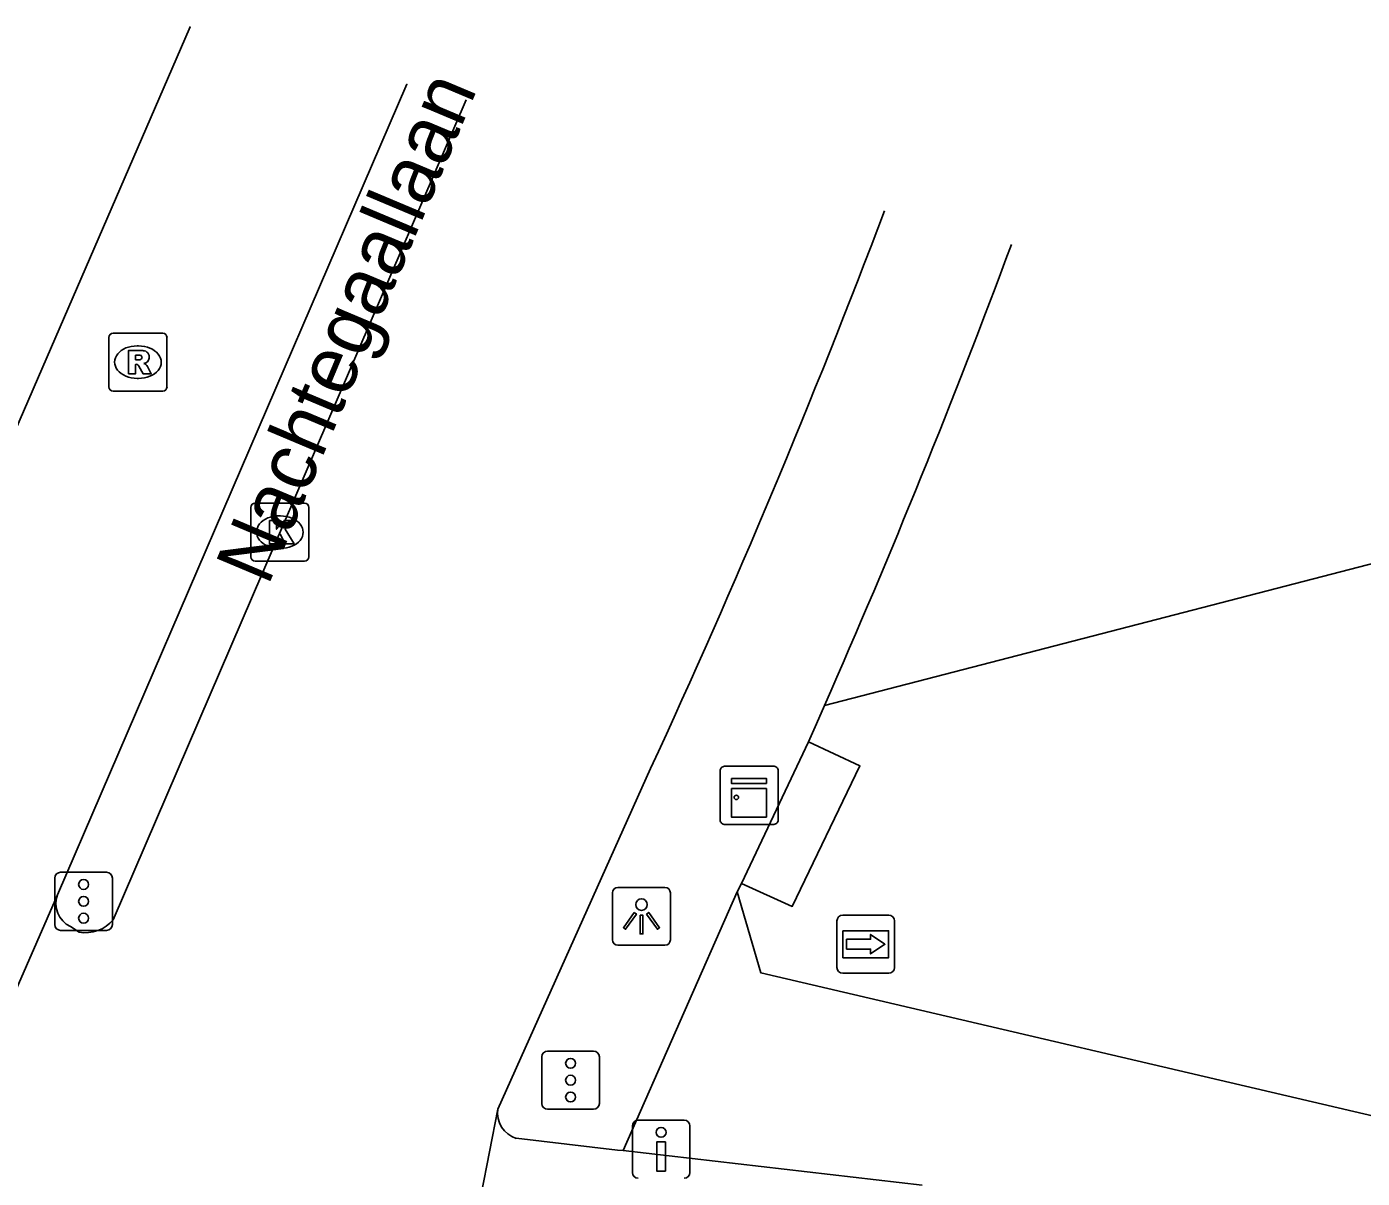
# Model space of a CAD drawing. Extents: x 161771 to 163125, y 382479 to 383177.
# Drawn here: x 161849.91 to 161872.88, y 383156.4 to 383176.21 of the extents above; entities that cross this region are included whole.
import ezdxf

# ---------------------------------------------------------------- set-up
doc = ezdxf.new("R2010")
doc.units = 0
for name, color, linetype in [('IMGEO_Drukknoppaal', 7, 'Continuous'), ('IMGEO_Fietspad_gesloten', 7, 'Continuous'), ('IMGEO_Groenvoorziening', 7, 'Continuous'), ('IMGEO_Kast', 7, 'Continuous'), ('IMGEO_Kolk', 7, 'Continuous'), ('IMGEO_Lichtpunt', 7, 'Continuous'), ('IMGEO_Openbare_ruimte_label', 7, 'Continuous'), ('IMGEO_Rijbaan_lokaal_gesloten', 7, 'Continuous'), ('IMGEO_Rioolput', 7, 'Continuous'), ('IMGEO_Verkeersregelinstallatiepaal', 7, 'Continuous'), ('IMGEO_Voetpad_open', 7, 'Continuous'), ('IMGEO_Wegwijzer', 7, 'Continuous')]:
    doc.layers.add(name, color=color, linetype=linetype)

msp = doc.modelspace()

# ---------------------------------------------------------------- linework, layer by layer
at = {"layer": 'IMGEO_Drukknoppaal'}
for p, q in [((161860.325, 383156.5), (161860.325, 383157.3)), ((161860.325, 383157.3), (161860.325, 383156.5)), ((161860.425, 383157.4), (161861.215, 383157.4)), ((161861.215, 383157.4), (161860.425, 383157.4)), ((161861.315, 383157.3), (161861.315, 383156.5)), ((161861.315, 383156.5), (161861.315, 383157.3))]:
    msp.add_line(p, q, dxfattribs=at)
msp.add_lwpolyline([(161860.895, 383157.025), (161860.895, 383156.525), (161860.745, 383156.525), (161860.745, 383157.025), (161860.895, 383157.025)], dxfattribs=at)
msp.add_circle((161860.82, 383157.19), 0.085, dxfattribs=at)
for centre, start, end in [((161860.425, 383157.3), 90, 180), ((161860.425, 383157.3), 90, 180), ((161861.215, 383157.3), 0, 90), ((161861.215, 383157.3), 360, 90), ((161860.425, 383156.5), 180, 270), ((161860.425, 383156.5), 180, 270), ((161861.215, 383156.5), 270, 0), ((161861.215, 383156.5), 270, 0)]:
    msp.add_arc(centre, 0.1, start, end, dxfattribs=at)
at = {"layer": 'IMGEO_Fietspad_gesloten'}
for points in [[(161852.715, 383176.208), (161852.715, 383176.208), (161847.31, 383163.743), (161846.264, 383161.291), (161846.152, 383161.028)], [(161856.447, 383175.219), (161856.447, 383175.219), (161850.438, 383161.277)], [(161858.326, 383157.088), (161860.068, 383156.887), (161860.165, 383156.876)], [(161865.311, 383156.282), (161860.165, 383156.876)]]:
    msp.add_lwpolyline(points, dxfattribs=at)
msp.add_arc((161858.469, 383157.53), 0.465, 172.5238, 252.0789, dxfattribs=at)
at = {"layer": 'IMGEO_Groenvoorziening'}
for points in [[(161863.63, 383164.532), (161876.472, 383167.861), (161877.756, 383169.569), (161877.756, 383169.569)], [(161863.354, 383163.909), (161864.239, 383163.493), (161863.075, 383161.077), (161862.205, 383161.47)]]:
    msp.add_lwpolyline(points, dxfattribs=at)
at = {"layer": 'IMGEO_Kast'}
for p, q in [((161861.91, 383163.488), (161862.751, 383163.488)), ((161862.751, 383163.488), (161861.91, 383163.488)), ((161861.835, 383162.563), (161861.835, 383163.404)), ((161861.835, 383163.404), (161861.835, 383162.563)), ((161862.835, 383163.413), (161862.835, 383162.572)), ((161862.835, 383162.572), (161862.835, 383163.413)), ((161862.76, 383162.488), (161861.919, 383162.488)), ((161861.919, 383162.488), (161862.76, 383162.488))]:
    msp.add_line(p, q, dxfattribs=at)
for points in [[(161862.03, 383163.278), (161862.63, 383163.278), (161862.63, 383163.193), (161862.03, 383163.193), (161862.03, 383163.278)], [(161862.03, 383163.103), (161862.63, 383163.103), (161862.63, 383162.614), (161862.03, 383162.614), (161862.03, 383163.103)]]:
    msp.add_lwpolyline(points, dxfattribs=at)
msp.add_circle((161862.114, 383162.952), 0.0377, dxfattribs=at)
for centre, start, end in [((161861.913, 383163.41), 92.4484, 184.2845), ((161861.913, 383163.41), 92.4484, 184.2845), ((161862.757, 383163.41), 2.4484, 94.2845), ((161862.757, 383163.41), 2.4484, 94.2845), ((161861.913, 383162.566), 182.4484, 274.2845), ((161861.913, 383162.566), 182.4484, 274.2845), ((161862.757, 383162.566), 272.4484, 4.2845), ((161862.757, 383162.566), 272.4484, 4.2845)]:
    msp.add_arc(centre, 0.0779, start, end, dxfattribs=at)
at = {"layer": 'IMGEO_Kolk'}
for p, q in [((161853.835, 383168.015), (161854.687, 383168.015)), ((161853.76, 383167.089), (161853.76, 383167.941)), ((161854.248, 383167.795), (161854.273, 383167.795)), ((161854.761, 383167.941), (161854.761, 383167.089)), ((161854.271, 383167.235), (161854.246, 383167.235)), ((161854.687, 383167.015), (161853.835, 383167.015))]:
    msp.add_line(p, q, dxfattribs=at)
for points in [[(161853.835, 383168.015), (161854.687, 383168.015)], [(161853.76, 383167.089), (161853.76, 383167.941)], [(161854.761, 383167.941), (161854.761, 383167.089)], [(161854.081, 383167.715), (161854.204, 383167.715), (161854.204, 383167.564), (161854.334, 383167.715), (161854.498, 383167.715), (161854.352, 383167.564), (161854.505, 383167.315), (161854.353, 383167.315), (161854.268, 383167.479), (161854.204, 383167.412), (161854.204, 383167.315), (161854.081, 383167.315), (161854.081, 383167.715)], [(161854.687, 383167.015), (161853.835, 383167.015)]]:
    msp.add_lwpolyline(points, dxfattribs=at)
for centre, start, end in [((161853.837, 383167.939), 91.552, 178.448), ((161853.837, 383167.939), 91.552, 178.448), ((161854.685, 383167.939), 1.552, 88.448), ((161854.685, 383167.939), 1.552, 88.448), ((161853.837, 383167.091), 181.552, 268.448), ((161853.837, 383167.091), 181.552, 268.448), ((161854.685, 383167.091), 271.552, 358.448), ((161854.685, 383167.091), 271.552, 358.448)]:
    msp.add_arc(centre, 0.0765, start, end, dxfattribs=at)
for centre, major_axis, ratio, start_param, end_param in [((161854.247, 383167.515), (-0.387, 0.002), 0.722429, 4.712389, 7.853982), ((161854.272, 383167.515), (-0.39, 0.002), 0.717154, 1.570796, 4.712389)]:
    msp.add_ellipse(centre, major_axis=major_axis, ratio=ratio, start_param=start_param, end_param=end_param, dxfattribs=at)
at = {"layer": 'IMGEO_Lichtpunt'}
for p, q in [((161860.885, 383161.405), (161860.077, 383161.405)), ((161860.885, 383161.405), (161860.077, 383161.405)), ((161859.983, 383161.31), (161859.983, 383160.503)), ((161859.983, 383161.31), (161859.983, 383160.503)), ((161860.979, 383160.503), (161860.979, 383161.31)), ((161860.979, 383160.503), (161860.979, 383161.31)), ((161860.077, 383160.409), (161860.885, 383160.409)), ((161860.077, 383160.409), (161860.885, 383160.409))]:
    msp.add_line(p, q, dxfattribs=at)
for points in [[(161860.357, 383160.974), (161860.396, 383160.946), (161860.208, 383160.684), (161860.17, 383160.711), (161860.357, 383160.974)], [(161860.459, 383160.926), (161860.506, 383160.926), (161860.506, 383160.604), (161860.459, 383160.604), (161860.459, 383160.926)], [(161860.569, 383160.946), (161860.607, 383160.973), (161860.794, 383160.711), (161860.755, 383160.683), (161860.569, 383160.946)]]:
    msp.add_lwpolyline(points, dxfattribs=at)
msp.add_circle((161860.482, 383161.108), 0.0994, dxfattribs=at)
for centre, start, end in [((161860.077, 383161.31), 90, 180), ((161860.077, 383161.31), 90, 180), ((161860.885, 383161.31), 0, 90), ((161860.885, 383161.31), 0, 90), ((161860.077, 383160.503), 180, 270), ((161860.077, 383160.503), 180, 270), ((161860.885, 383160.503), 270, 0), ((161860.885, 383160.503), 270, 360)]:
    msp.add_arc(centre, 0.0946, start, end, dxfattribs=at)
at = {"layer": 'IMGEO_Rijbaan_lokaal_gesloten'}
for points in [[(161851.391, 383160.847), (161857.465, 383174.949), (161857.465, 383174.949)], [(161858.008, 383157.591), (161860.639, 383163.447)], [(161850.438, 383161.277), (161841.823, 383141.564), (161840.322, 383138.503), (161840.254, 383138.363)], [(161850.66, 383160.732), (161850.806, 383160.634)], [(161857.437, 383154.654), (161858.008, 383157.591)]]:
    msp.add_lwpolyline(points, dxfattribs=at)
for centre, radius, start, end in [((161725.904, 383225.605), 148.382, 335.23443, 339.25215), ((161728.746, 383224.589), 145.364, 339.23, 339.23027), ((161850.835, 383161.121), 0.427, 158.5475, 245.7785), ((161850.919, 383161.234), 0.61, 259.3262, 320.6872)]:
    msp.add_arc(centre, radius, start, end, dxfattribs=at)
at = {"layer": 'IMGEO_Rioolput'}
for p, q in [((161851.318, 383170.013), (161851.318, 383170.865)), ((161851.393, 383170.939), (161852.245, 383170.939)), ((161852.319, 383170.865), (161852.319, 383170.013)), ((161851.806, 383170.719), (161851.831, 383170.719)), ((161851.829, 383170.159), (161851.804, 383170.159)), ((161852.245, 383169.939), (161851.393, 383169.939))]:
    msp.add_line(p, q, dxfattribs=at)
for points in [[(161851.318, 383170.013), (161851.318, 383170.865)], [(161851.393, 383170.939), (161852.245, 383170.939)], [(161852.319, 383170.865), (161852.319, 383170.013)], [(161851.907, 383170.637), (161851.655, 383170.639), (161851.655, 383170.239)], [(161851.833, 383170.558), (161851.779, 383170.558), (161851.779, 383170.477)], [(161851.655, 383170.239), (161851.779, 383170.239), (161851.779, 383170.401), (161851.79, 383170.401)], [(161851.779, 383170.477), (161851.831, 383170.477)], [(161851.837, 383170.372), (161851.908, 383170.239), (161852.048, 383170.239), (161851.983, 383170.365)], [(161852.245, 383169.939), (161851.393, 383169.939)]]:
    msp.add_lwpolyline(points, dxfattribs=at)
for centre, radius, start, end in [((161851.395, 383170.863), 0.0765, 91.552, 178.448), ((161851.395, 383170.863), 0.0765, 91.552, 178.448), ((161852.243, 383170.863), 0.0765, 1.552, 88.448), ((161852.243, 383170.863), 0.0765, 1.552, 88.448), ((161851.839, 383170.462), 0.0964, 77.0061, 93.1865), ((161851.853, 383170.519), 0.0378, 276.6634, 79.6772), ((161851.906, 383170.527), 0.109, 350.3612, 89.416), ((161851.789, 383170.348), 0.0533, 26.0293, 88.6989), ((161851.815, 383170.666), 0.19, 274.7715, 282.9687), ((161851.904, 383170.527), 0.112, 277.5842, 350.9817), ((161851.888, 383170.312), 0.108, 29.5134, 73.7905), ((161851.395, 383170.015), 0.0765, 181.552, 268.448), ((161851.395, 383170.015), 0.0765, 181.552, 268.448), ((161852.243, 383170.015), 0.0765, 271.552, 358.448), ((161852.243, 383170.015), 0.0765, 271.552, 358.448)]:
    msp.add_arc(centre, radius, start, end, dxfattribs=at)
for centre, major_axis, ratio, start_param, end_param in [((161851.805, 383170.439), (-0.387, 0.002), 0.722429, 4.712389, 7.853982), ((161851.83, 383170.439), (-0.39, 0.002), 0.717154, 1.570796, 4.712389)]:
    msp.add_ellipse(centre, major_axis=major_axis, ratio=ratio, start_param=start_param, end_param=end_param, dxfattribs=at)
at = {"layer": 'IMGEO_Verkeersregelinstallatiepaal'}
for p, q in [((161850.489, 383161.664), (161851.279, 383161.664)), ((161851.279, 383161.664), (161850.489, 383161.664)), ((161850.389, 383160.764), (161850.389, 383161.564)), ((161850.389, 383161.564), (161850.389, 383160.764)), ((161851.379, 383161.564), (161851.379, 383160.764)), ((161851.379, 383160.764), (161851.379, 383161.564)), ((161851.279, 383160.664), (161850.489, 383160.664)), ((161850.489, 383160.664), (161851.279, 383160.664)), ((161858.767, 383157.688), (161858.767, 383158.488)), ((161858.767, 383158.488), (161858.767, 383157.688)), ((161858.867, 383158.588), (161859.657, 383158.588)), ((161859.657, 383158.588), (161858.867, 383158.588)), ((161859.757, 383158.488), (161859.757, 383157.688)), ((161859.757, 383157.688), (161859.757, 383158.488)), ((161859.657, 383157.588), (161858.867, 383157.588)), ((161858.867, 383157.588), (161859.657, 383157.588))]:
    msp.add_line(p, q, dxfattribs=at)
for centre in [(161850.884, 383161.454), (161850.884, 383161.164), (161850.884, 383160.874), (161859.262, 383158.378), (161859.262, 383158.088), (161859.262, 383157.798)]:
    msp.add_circle(centre, 0.085, dxfattribs=at)
for centre, start, end in [((161850.489, 383161.564), 90, 180), ((161850.489, 383161.564), 90, 180), ((161851.279, 383161.564), 0, 90), ((161851.279, 383161.564), 360, 90), ((161850.489, 383160.764), 180, 270), ((161850.489, 383160.764), 180, 270), ((161851.279, 383160.764), 270, 0), ((161851.279, 383160.764), 270, 0), ((161858.867, 383158.488), 90, 180), ((161858.867, 383158.488), 90, 180), ((161859.657, 383158.488), 0, 90), ((161859.657, 383158.488), 360, 90), ((161858.867, 383157.688), 180, 270), ((161858.867, 383157.688), 180, 270), ((161859.657, 383157.688), 270, 0), ((161859.657, 383157.688), 270, 0)]:
    msp.add_arc(centre, 0.1, start, end, dxfattribs=at)
at = {"layer": 'IMGEO_Voetpad_open'}
for points in [[(161863.354, 383163.909), (161863.492, 383164.22), (161863.63, 383164.532)], [(161862.205, 383161.47), (161863.354, 383163.909)], [(161862.13, 383161.327), (161862.205, 383161.47)], [(161860.165, 383156.876), (161862.13, 383161.327)], [(161862.13, 383161.327), (161862.538, 383159.933), (161873.619, 383157.344)]]:
    msp.add_lwpolyline(points, dxfattribs=at)
for centre, radius, start, end in [((161728.354, 383224.04), 147.786, 336.25507, 339.57257), ((161719.189, 383227.294), 157.511, 339.62699, 339.62756)]:
    msp.add_arc(centre, radius, start, end, dxfattribs=at)
at = {"layer": 'IMGEO_Wegwijzer'}
for p, q in [((161863.945, 383160.927), (161864.735, 383160.927)), ((161864.735, 383160.927), (161863.945, 383160.927)), ((161863.845, 383160.027), (161863.845, 383160.827)), ((161863.845, 383160.827), (161863.845, 383160.027)), ((161864.835, 383160.827), (161864.835, 383160.027)), ((161864.835, 383160.027), (161864.835, 383160.827)), ((161864.735, 383159.927), (161863.945, 383159.927)), ((161863.945, 383159.927), (161864.735, 383159.927))]:
    msp.add_line(p, q, dxfattribs=at)
for points in [[(161863.946, 383160.659), (161864.734, 383160.659), (161864.734, 383160.195), (161863.946, 383160.195), (161863.946, 383160.659)], [(161864.011, 383160.511), (161864.011, 383160.427), (161864.011, 383160.343), (161864.422, 383160.343), (161864.422, 383160.26), (161864.669, 383160.427), (161864.422, 383160.594), (161864.422, 383160.511), (161864.011, 383160.511)]]:
    msp.add_lwpolyline(points, dxfattribs=at)
for centre, start, end in [((161863.945, 383160.827), 90, 180), ((161863.945, 383160.827), 90, 180), ((161864.735, 383160.827), 0, 90), ((161864.735, 383160.827), 360, 90), ((161863.945, 383160.027), 180, 270), ((161863.945, 383160.027), 180, 270), ((161864.735, 383160.027), 270, 0), ((161864.735, 383160.027), 270, 0)]:
    msp.add_arc(centre, 0.1, start, end, dxfattribs=at)

# ---------------------------------------------------------------- texts
at = {"layer": 'IMGEO_Openbare_ruimte_label'}
msp.add_text('Nachtegaallaan', height=1, rotation=67.1775, dxfattribs=at).set_placement((161854.056, 383166.571))

doc.saveas('drawing.dxf')
